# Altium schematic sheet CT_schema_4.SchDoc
size 339 x 183 mm
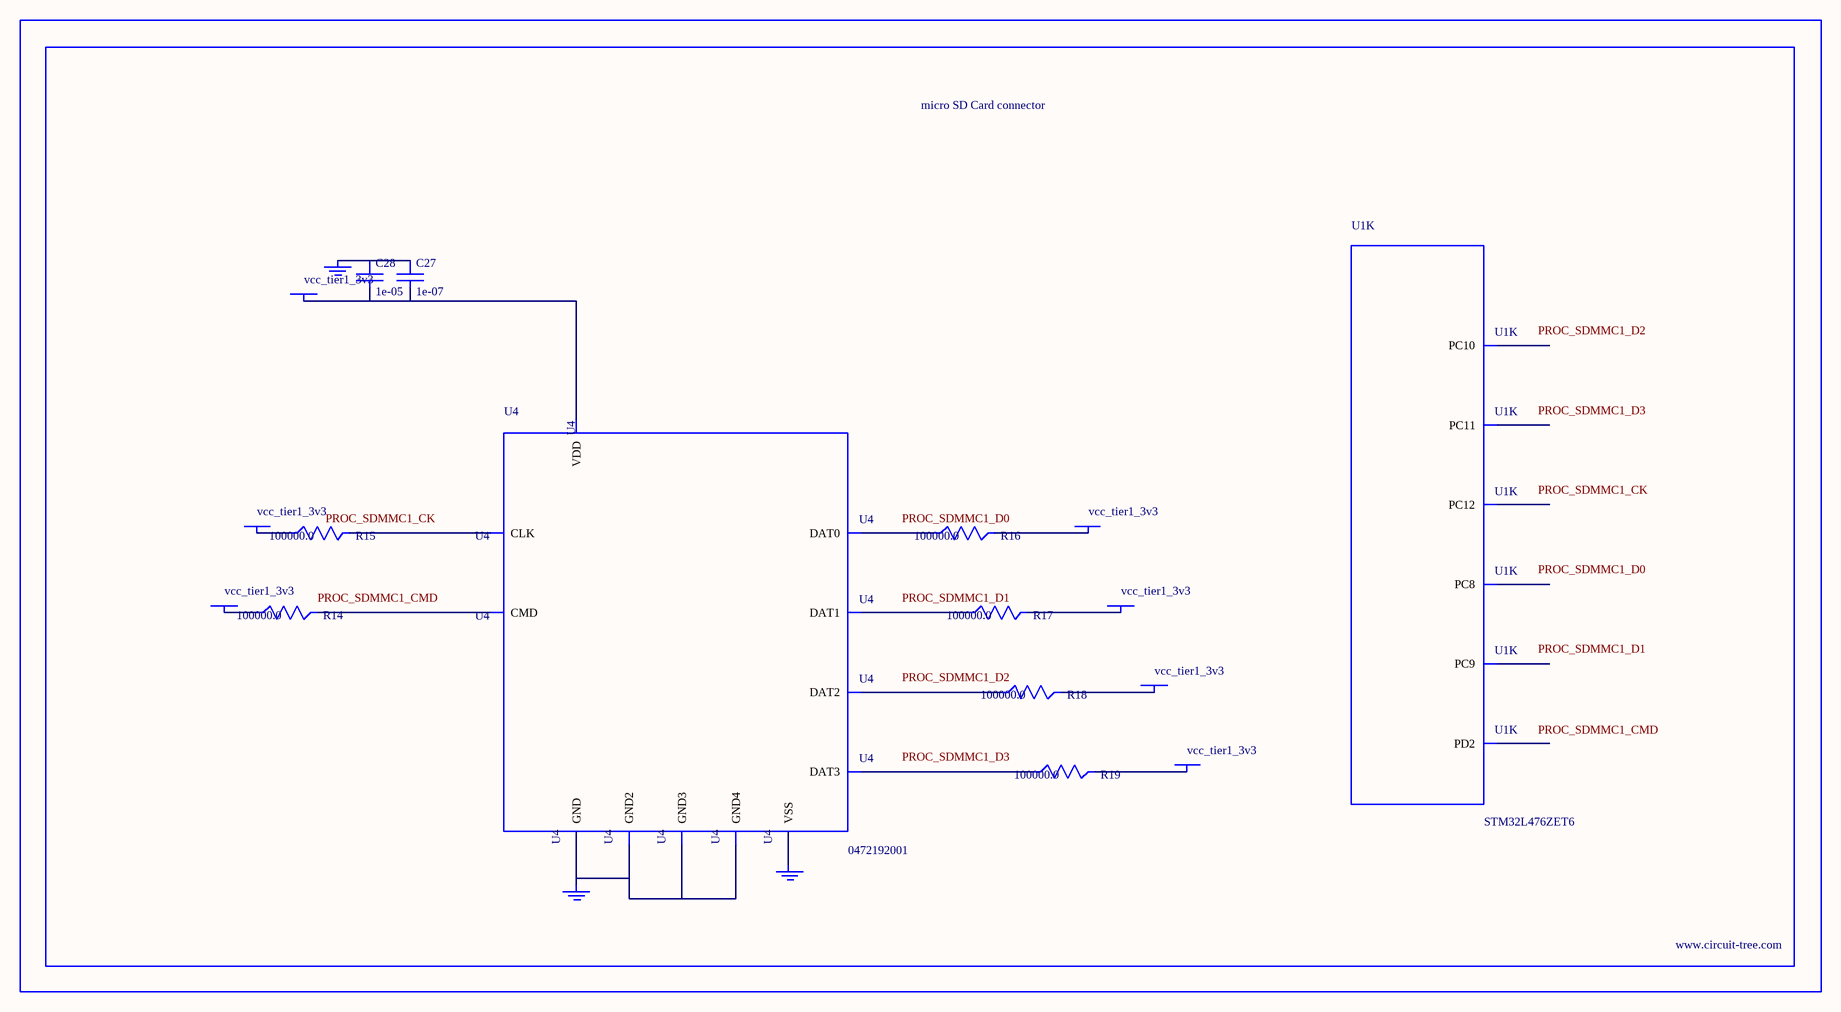
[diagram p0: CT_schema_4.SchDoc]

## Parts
BORDER3  (no value)
C27  1e-07  [C0402]
C28  1e-05  [C0805]
GND_INSTANCE_3_0  (no value)
GND_INSTANCE_3_1  (no value)
GND_INSTANCE_3_2  (no value)
POWER_INSTANCE_3_0  vcc_tier1_3v3
POWER_INSTANCE_3_1  vcc_tier1_3v3
POWER_INSTANCE_3_2  vcc_tier1_3v3
POWER_INSTANCE_3_3  vcc_tier1_3v3
POWER_INSTANCE_3_4  vcc_tier1_3v3
POWER_INSTANCE_3_5  vcc_tier1_3v3
POWER_INSTANCE_3_6  vcc_tier1_3v3
R14  100000.0  [R0603]
R15  100000.0  [R0603]
R16  100000.0  [R0603]
R17  100000.0  [R0603]
R18  100000.0  [R0603]
R19  100000.0  [R0603]
U1  STM32L476ZET6  [LQFP144]  (part K of 13)
U4  0472192001  [MOLEX_47219-2001]

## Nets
NetC27_1: C27.1 C28.1 GND_INSTANCE_3_0.0(GND)
NetC27_2: C27.2 C28.2 POWER_INSTANCE_3_3.0(PWR) U4.4(VDD)
NetGND_INSTANCE_3_1_0: GND_INSTANCE_3_1.0(GND) U4.6(VSS)
NetGND_INSTANCE_3_2_0: GND_INSTANCE_3_2.0(GND) U4.G1(GND) U4.G2(GND2) U4.G3(GND3) U4.G4(GND4)
NetPOWER_INSTANCE_3_0_0: POWER_INSTANCE_3_0.0(PWR) R18.2
NetPOWER_INSTANCE_3_1_0: POWER_INSTANCE_3_1.0(PWR) R19.2
NetPOWER_INSTANCE_3_2_0: POWER_INSTANCE_3_2.0(PWR) R14.1
NetPOWER_INSTANCE_3_4_0: POWER_INSTANCE_3_4.0(PWR) R15.1
NetPOWER_INSTANCE_3_5_0: POWER_INSTANCE_3_5.0(PWR) R16.2
NetPOWER_INSTANCE_3_6_0: POWER_INSTANCE_3_6.0(PWR) R17.2
NetR14_2: R14.2 U4.3(CMD)
NetR15_2: R15.2 U4.5(CLK)
NetR16_1: R16.1 U4.7(DAT0)
NetR17_1: R17.1 U4.8(DAT1)
NetR18_1: R18.1 U4.1(DAT2)
NetR19_1: R19.1 U4.2(DAT3)

Not connected (* = marked no-connect by the designer): U1 98(PC8) 99(PC9) 111(PC10) 112(PC11) 113(PC12) 116(PD2)

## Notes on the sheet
- Labels drawn without touching a wire or pin: PROC_SDMMC1_CK, PROC_SDMMC1_CMD, PROC_SDMMC1_D0, PROC_SDMMC1_D1, PROC_SDMMC1_D2, PROC_SDMMC1_D3

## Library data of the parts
BORDER3 = BORDER_PAGE3
C27 = C0402C104K3RACTU
C28 = C0805C106K8RACTU
GND_INSTANCE_3_0-GND_INSTANCE_3_2 = GND
POWER_INSTANCE_3_0-POWER_INSTANCE_3_6 = PWR
R14-R19 = RC0603JR-07100KL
